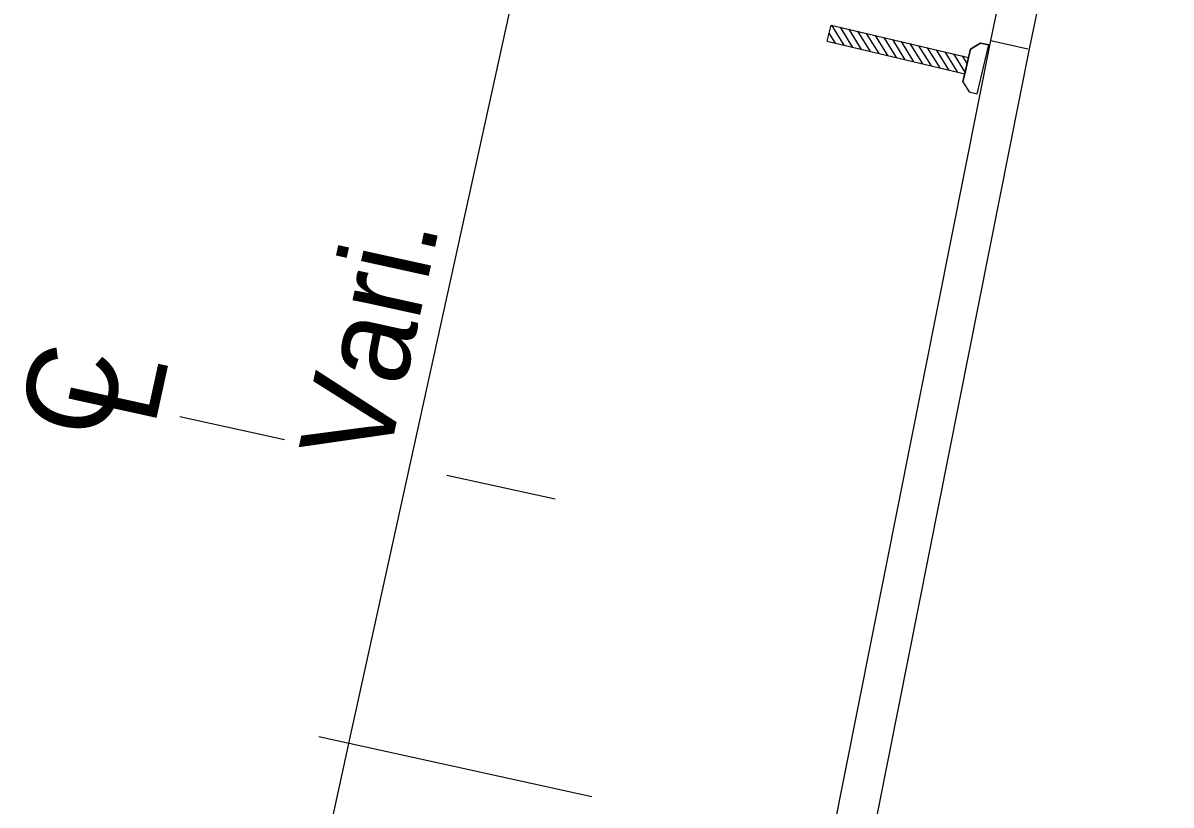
# Model space of a CAD drawing. Extents: x 14104283 to 14128447, y 8633203 to 8671666.
# Drawn here: x 14107411.4 to 14107513.2, y 8639323.3 to 8639392.7 of the extents above; entities that cross this region are included whole.
import ezdxf

# ---------------------------------------------------------------- set-up
doc = ezdxf.new("R2010")
doc.units = 0
for name, color, linetype in [('Cell', 7, 'Continuous'), ('dsnTextFinalPlan', 7, 'Continuous'), ('TC_SubstrataExistingPavement', 7, 'Continuous'), ('Terrain', 7, 'Continuous')]:
    doc.layers.add(name, color=color, linetype=linetype)

msp = doc.modelspace()

# ---------------------------------------------------------------- linework, layer by layer
at = {"layer": 'Cell'}
for p, q in [((14107482.68, 8639391.08), (14107483.02, 8639392.52)), ((14107483.02, 8639392.52), (14107495.21, 8639389.66)), ((14107484.18, 8639390.73), (14107483.07, 8639392.51)), ((14107484.95, 8639390.54), (14107483.85, 8639392.33)), ((14107485.72, 8639390.36), (14107484.62, 8639392.15)), ((14107486.5, 8639390.18), (14107485.39, 8639391.97)), ((14107482.68, 8639391.08), (14107494.87, 8639388.21)), ((14107483.41, 8639390.91), (14107482.85, 8639391.8)), ((14107487.27, 8639390), (14107486.17, 8639391.78)), ((14107488.04, 8639389.82), (14107486.94, 8639391.6)), ((14107488.82, 8639389.64), (14107487.71, 8639391.42)), ((14107489.59, 8639389.45), (14107488.48, 8639391.24)), ((14107490.36, 8639389.27), (14107489.26, 8639391.06)), ((14107491.14, 8639389.09), (14107490.03, 8639390.88)), ((14107496.27, 8639390.93), (14107495.38, 8639390.38)), ((14107495.38, 8639390.38), (14107496.27, 8639390.93)), ((14107496.99, 8639390.77), (14107496.27, 8639390.93)), ((14107496.27, 8639390.93), (14107496.99, 8639390.77)), ((14107491.91, 8639388.91), (14107490.8, 8639390.69)), ((14107492.68, 8639388.73), (14107491.58, 8639390.51)), ((14107493.46, 8639388.54), (14107492.35, 8639390.33)), ((14107494.23, 8639388.36), (14107493.12, 8639390.15)), ((14107494.9, 8639388.34), (14107493.9, 8639389.97)), ((14107494.7, 8639387.49), (14107495.38, 8639390.38)), ((14107495.38, 8639390.38), (14107495.21, 8639389.66)), ((14107495.97, 8639386.43), (14107496.99, 8639390.77)), ((14107495.97, 8639386.43), (14107496.99, 8639390.77)), ((14107495.09, 8639389.11), (14107494.67, 8639389.79)), ((14107495.21, 8639389.66), (14107494.87, 8639388.21)), ((14107494.87, 8639388.21), (14107494.7, 8639387.49)), ((14107494.7, 8639387.49), (14107495.25, 8639386.6)), ((14107494.7, 8639387.49), (14107495.25, 8639386.6)), ((14107495.25, 8639386.6), (14107495.97, 8639386.43)), ((14107495.25, 8639386.6), (14107495.97, 8639386.43))]:
    msp.add_line(p, q, dxfattribs=at)
at = {"layer": 'dsnTextFinalPlan'}
for p, q in [((14107440.25, 8639328.81), (14107455.37, 8639397.63)), ((14107425.26, 8639357.8), (14107434.55, 8639355.76)), ((14107448.95, 8639352.6), (14107458.56, 8639350.49)), ((14107429.95, 8639281.93), (14107440.25, 8639328.81)), ((14107461.8, 8639324.07), (14107437.58, 8639329.39))]:
    msp.add_line(p, q, dxfattribs=at)
at = {"layer": 'TC_SubstrataExistingPavement'}
msp.add_line((14107497.18, 8639391.15), (14107500.47, 8639390.42), dxfattribs=at)
msp.add_lwpolyline([(14107513.16, 8639450.46), (14107500.59, 8639390.4), (14107481.87, 8639296.22), (14107478.45, 8639296.97)], dxfattribs=at)
at = {"layer": 'Terrain'}
msp.add_lwpolyline([(14107471.43, 8639257.56), (14107478.45, 8639296.97), (14107497.18, 8639391.15), (14107509.74, 8639451.21)], dxfattribs=at)

# ---------------------------------------------------------------- texts
at = {"layer": 'dsnTextFinalPlan'}
for s, p in [('Vari.', (14107443.61, 8639353.32)), ('C', (14107418.76, 8639355.52)), ('L', (14107423.01, 8639356.83))]:
    msp.add_text(s, height=8, rotation=77.6078, dxfattribs=at).set_placement(p)

doc.saveas('drawing.dxf')
